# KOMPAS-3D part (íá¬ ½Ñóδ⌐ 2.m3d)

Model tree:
1. Эскиз:1
2. Операция выдавливания:1
     Расстояние 1 = 11
3. Эскиз:2
4. Вырезать элемент выдавливания:1
     Расстояние 1 = 34.8
5. Скругление:1
     Радиус = 1
6. Скругление:2
     Радиус = 2
7. Эскиз:3
8. Вырезать элемент выдавливания:2
     Расстояние 1 = 0.2
9. Скругление:3
     Радиус = 0.2
10. Эскиз:4
11. Операция выдавливания:2
     Расстояние 1 = 2; Расстояние 2 = 4.9
12. Скругление:4
     Радиус = 1
13. Эскиз:5
14. Вырезать элемент выдавливания:3
     Расстояние 1 = 0.2
15. Скругление:6
     Радиус = 0.1
16. Эскиз:6
17. Операция выдавливания:3
     Расстояние 1 = 0.1; Расстояние 2 = 4.9

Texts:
  бак левый 2
  Сплав АЛ8  ГОСТ 1583-93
